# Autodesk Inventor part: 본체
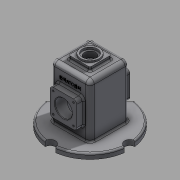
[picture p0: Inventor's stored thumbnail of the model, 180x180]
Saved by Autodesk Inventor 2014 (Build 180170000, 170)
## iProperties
Created: 2018-07
Part Number: 본체
Material: Generic
Document SubType Name: Modeling
Designer: user
Density: 1 g/cm^3
Appearance: Default
Author: user
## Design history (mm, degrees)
sketch "Sketch1"
  geometry: C1 r 75 at (0, 0); 1 further point
  constraints: 1 centre point, 1 coincident
  dimensions: "d0" = 150 diameter of C1
extrude "Extrusion1" new body sketch "Sketch1" distance "d1" = 10; taper "d2" = 0 deg
sketch "Sketch2"
  geometry: L1 (0, 0)-(0, 121.11); C1 r 10 at (0, 75)
  constraints: 2 end point, 1 centre point, 1 vertical, 1 vertical alignment, 1 other
  dimensions: "d3" = 20 diameter of C1; "d4" = 0 distance from line of C1.centre L1
extrude "Extrusion2" cut sketch "Sketch2" distance "d5" = 10; taper "d6" = 0 deg
pattern_circular "Circular Pattern1" dims angle "d8" = 360 deg
sketch "Sketch3"
  geometry: L1 (-37, 37)-(37, 37); L2 (37, 37)-(37, -37); L3 (37, -37)-(-37, -37); L4 (-37, -37)-(-37, 37); L5 (0, 0)-(153.232, 0); L6 (0, 0)-(0, 243.546); A1 r 75 centre (0, 0) between (9.978, -74.333) and (74.333, -9.978) reference
  constraints: 12 end point, 3 perpendicular, 2 parallel, 1 horizontal, 2 other
  dimensions: "d10" = 74 distance between parallel lines of L4 L2; "d11" = 74 distance between parallel lines of L3 L1
extrude "Extrusion3" join sketch "Sketch3" distance "d12" = 100; taper "d13" = 0 deg
workplane "Work Plane1"
sketch "Sketch4"
  geometry: L1 (12, 70)-(62, 70); L2 (62, 70)-(62, 20); L3 (62, 20)-(12, 20); L4 (12, 20)-(12, 70); L5 (-38.534, 45)-(101.823, 45); L6 (37, 113.812)-(37, 3.906); L7 (46.978, -10)-(111.333, -10) reference; L8 (74, 0)-(74, 100) reference; 1 further point
  constraints: 12 end point, 3 perpendicular, 2 parallel, 1 horizontal, 2 other
  dimensions: "d16" = 50 distance between parallel lines of L3 L1; "d17" = 50 distance between parallel lines of L4 L2; "d18" = 55 distance between parallel lines of L5 L7; "d20" = 37 distance between parallel lines of L6 L8
extrude "Extrusion4" join sketch "Sketch4" distance "d21" = 100; taper "d22" = 0 deg
sketch "Sketch5"
  geometry: L1 (-12, 70)-(-62, 70) reference; L2 (-12, 20)-(-12, 70) reference; C1 r 16 at (-37, 45); 1 further point
  constraints: 1 centre point
  dimensions: "d23" = 32 diameter of C1; "d26" = 25 distance from line of L2 C1.centre; "d27" = 25 distance from line of C1.centre L1
extrude "Extrusion5" cut sketch "Sketch5" distance "d28" = 100; taper "d29" = 0 deg
chamfer "Chamfer1" distance "d30" = 1; stored, may be unused: second distance "d31" = 2, angle "d32" = 45 deg
fillet "Fillet1" dims "d33" = 6
fillet "Fillet2" dims "d34" = 3
sketch "Sketch6"
  geometry: A1 r 6 centre (18, 26) between (12, 26) and (18, 20) reference; A2 r 6 centre (56, 26) between (56, 20) and (62, 26) reference; A3 r 6 centre (56, 64) between (62, 64) and (56, 70) reference; A4 r 6 centre (18, 64) between (18, 70) and (12, 64) reference; 5 further points
  constraints: 4 coincident
hole "Hole1" sketch "Sketch6" at (18, 64), (56, 64), (56, 26), (18, 26) diameter "d35" = 3.242; stored, may be unused: countersink angle "d39" = 82 deg, drill point angle "d41" = 118 deg; dims "d36" = 8, "d37" = 3.023, "d38" = 2, "d40" = 10
mirror "Mirror1"
fillet "Fillet3" dims "d42" = 8
fillet "Fillet4" dims "d43" = 8
fillet "Fillet5" dims "d44" = 3
fillet "Fillet6" dims "d45" = 3
sketch "Sketch7"
  geometry: L1 (-20, 20)-(20, 20); L2 (20, 20)-(20, -20); L3 (20, -20)-(-20, -20); L4 (-20, -20)-(-20, 20); 1 further point
  constraints: 8 end point, 2 parallel, 1 horizontal, 1 perpendicular
  dimensions: "d46" = 40 distance between parallel lines of L4 L2; "d47" = 40 distance between parallel lines of L3 L1; "d48" = 20 distance from line of L1 point (0, 0); "d49" = 20 distance from line of point (0, 0) L2
extrude "Extrusion6" join sketch "Sketch7" distance "d50" = 7; taper "d51" = 0 deg
sketch "Sketch8"
  geometry: C1 r 17.5 at (0, 0); 1 further point
  constraints: 1 centre point, 1 coincident
  dimensions: "d52" = 35 diameter of C1
extrude "Extrusion7" join sketch "Sketch8" distance "d53" = 3; taper "d54" = 0 deg
sketch "Sketch9"
  geometry: L1 (0, 0)-(0, 389.433); L2 (0, 105)-(32, 105); L3 (32, 0)-(0, 0); L4 (9.978, 0)-(74.333, 0) reference; L5 (-29, 110)-(29, 110) reference; L6 (32, 75)-(25, 75); L7 (25, 75)-(25, 35); L8 (25, 35)-(32, 35); L9 (32, 105)-(32, 75); L10 (32, 35)-(32, 0); L11 (-62.016, 55)-(68.351, 55); L12 (0, 105)-(-32, 105); L13 (-32, 105)-(-32, 75); L14 (-32, 75)-(-25, 75); L15 (-25, 75)-(-25, 35); L16 (-25, 35)-(-32, 35); L17 (-32, 35)-(-32, 0); L18 (-32, 0)-(0, 0)
  constraints: 32 end point, 6 symmetric about line, 4 perpendicular, 3 parallel, 2 point on line, 1 collinear, 1 horizontal, 1 vertical, 1 other
  dimensions: "d88" = 0 distance between parallel lines of L3 L4; "d90" = 5 distance between parallel lines of L5 L2; "d93" = 32 distance between parallel lines of L1 L10; "d94" = 7 distance between parallel lines of L9 L7; "d95" = 55 distance between parallel lines of L4 L11; "d96" = 40 distance between parallel lines of L8 L6
sketch "Sketch10"
  geometry: L1 (0, 0)-(0, 198.492); L2 (32, 80)-(22, 76.36); L3 (22, 76.36)-(22, 33.64); L4 (22, 33.64)-(32, 30); L5 (32, 80)-(32, 30); L6 (-17.49, 55)-(69.252, 55); L7 (9.978, 0)-(74.333, 0) reference
  constraints: 12 end point, 1 parallel, 1 perpendicular, 1 vertical
  dimensions: "d67" = 110 deg angle of L4 L5; "d68" = 110 deg angle of L2 L5; "d70" = 10 distance between parallel lines of L3 L5; "d71" = 50 distance of L4.end L2.start; "d72" = 25 distance from line of L6 L2.start; "d73" = 55 distance between parallel lines of L7 L6; "d74" = 64 diameter of L5 L1
extrude "Extrusion11" cut sketch "Sketch9" stored distance "d97" = 64; taper "d98" = 0 deg
revolve "Revolution1" stored, may be unused: angle "d99" = 90 deg
sketch "Sketch11"
  geometry: L1 (0, 0)-(0, 277.521); L2 (14, 120)-(14, 116); L3 (14, 116)-(10.5, 116); L4 (10.5, 116)-(10.5, 105); L5 (17.5, 120)-(-17.5, 120) reference; L6 (10.5, 105)-(0, 105); L7 (14, 120)-(0, 120); L8 (0, 120)-(0, 105); L9 (-29, 110)-(29, 110) reference
  constraints: 14 end point, 3 parallel, 2 point on line, 1 collinear, 1 midpoint, 1 perpendicular, 1 vertical
  dimensions: "d100" = 21 diameter of L4 L1; "d101" = 4 distance between parallel lines of L3 L5; "d102" = 28 diameter of L2 L1; "d103" = 5 distance between parallel lines of L6 L9
revolve "Revolution2" sketch "Sketch11" stored, may be unused: angle "d104" = 90 deg
fillet "Fillet7" dims "d105" = 3
fillet "Fillet8" dims "d106" = 3
sketch "Sketch12"
  geometry: L1 (6.108, -10.61)-(51.892, -10.61); L2 (51.892, -10.61)-(51.892, -13.39); L3 (51.892, -13.39)-(6.108, -13.39); L4 (6.108, -13.39)-(6.108, -10.61); L5 (-7.142, -12)-(65.536, -12); L6 (29, -2.071)-(29, -38.646); L7 (66, -89)-(66, 0) reference; L8 (46.5, 18)-(11.5, 18) reference; 1 further point
  constraints: 4 end point, 2 perpendicular, 4 other
  dimensions: "d107" = 37 distance between parallel lines of L7 L6; "d108" = 30 distance between parallel lines of L5 L8
extrude "Extrusion12" join sketch "Sketch12" distance "d109" = 0.5; taper "d110" = 0 deg
body "Solid1"
other parameters: "d14" = 13, "d61" = 64, "d79" = 110 deg, "d80" = 110 deg, "d89" = 64
